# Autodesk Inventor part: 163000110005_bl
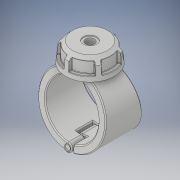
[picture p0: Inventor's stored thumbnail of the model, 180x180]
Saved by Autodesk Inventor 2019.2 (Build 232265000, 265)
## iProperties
Created: 2022-02
Part Number: 163000110005_bl
Material: Generic
Description: Plassadle Threaded 110x1/2''
Document SubType Name: Modeling
Designer: comp2
Density: 1 g/cm^3
Appearance: Default
Author: comp2
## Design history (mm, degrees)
derived "16300.ipt"
feature "Solid1::16300.ipt" dims "ScaleForDerivedMember" = 10
feature "Solid2::16300.ipt" dims "ScaleForDerivedMember" = 10
feature "Solid3::16300.ipt" dims "ScaleForDerivedMember" = 10
feature "Solid4::16300.ipt" dims "ScaleForDerivedMember" = 10
tag "TaggingFeature1"
body "Solid1"
body "Solid2"
body "Solid3"
body "Solid4"
other parameters: "d2" = 141 [user parameter], "d3" = 55 [user parameter], "d7" = 133.95 [user parameter], "d8" = 85 deg [user parameter], "d9" = 45 deg [user parameter], "d10" = 102 [user parameter], "d11" = 49 [user parameter], "d12" = 27.7935 [user parameter], "d13" = 42.84 [user parameter], "d14" = 27.9465 [user parameter], "d42" = 3.1 [user parameter], "d49" = 2.82 [user parameter], "d50" = 97 [user parameter], "d51" = 0 [user parameter], "d52" = 21.7 [user parameter], "d53" = 77.55 [user parameter], "d54" = 33.95 [user parameter], "d55" = 0 [user parameter], "d56" = 19.4 [user parameter], "d57" = 19.4 [user parameter], "d59" = 0 [user parameter], "d60" = 97 [user parameter], "d61" = 0 [user parameter], "d62" = 33.95 [user parameter], "d63" = 0 [user parameter], "d65" = 0 [user parameter], "d67" = 0 [user parameter], "d69" = 0 [user parameter], "d70" = 1 [user parameter], "d71" = 93.12 [user parameter], "d72" = 0 [user parameter], "d73" = 2 [user parameter], "d78" = 86.7 [user parameter], "d79" = 5.1 [user parameter], "d80" = 60 deg [user parameter], "d81" = 5.1 [user parameter], "d84" = 0 [user parameter], "d85" = 1 [user parameter], "d87" = 360 deg [user parameter], "d122" = 49 [user parameter], "d124" = 42.80128 [user parameter], "d125" = 1.98525 [user parameter], "d129" = 18.631 [user parameter], "d130" = 15.83635 [user parameter], "d131" = 31.85 [user parameter], "d132" = 45 deg [user parameter], "d133" = 22.295 [user parameter], "d134" = 9.3155 [user parameter], "d136" = 0 [user parameter], "d138" = 0 [user parameter], "d1" = 25 [user parameter], "B" = 141 [user parameter], "L" = 97 [user parameter], "E_" = 54 [user parameter], "E1" = 102 [user parameter], "H2" = 49 [user parameter], "H3" = 78 [user parameter], "H_costum" = 49 [user parameter], "Rp" = 18.631 [user parameter], "d128" = 39.705 [user parameter]
